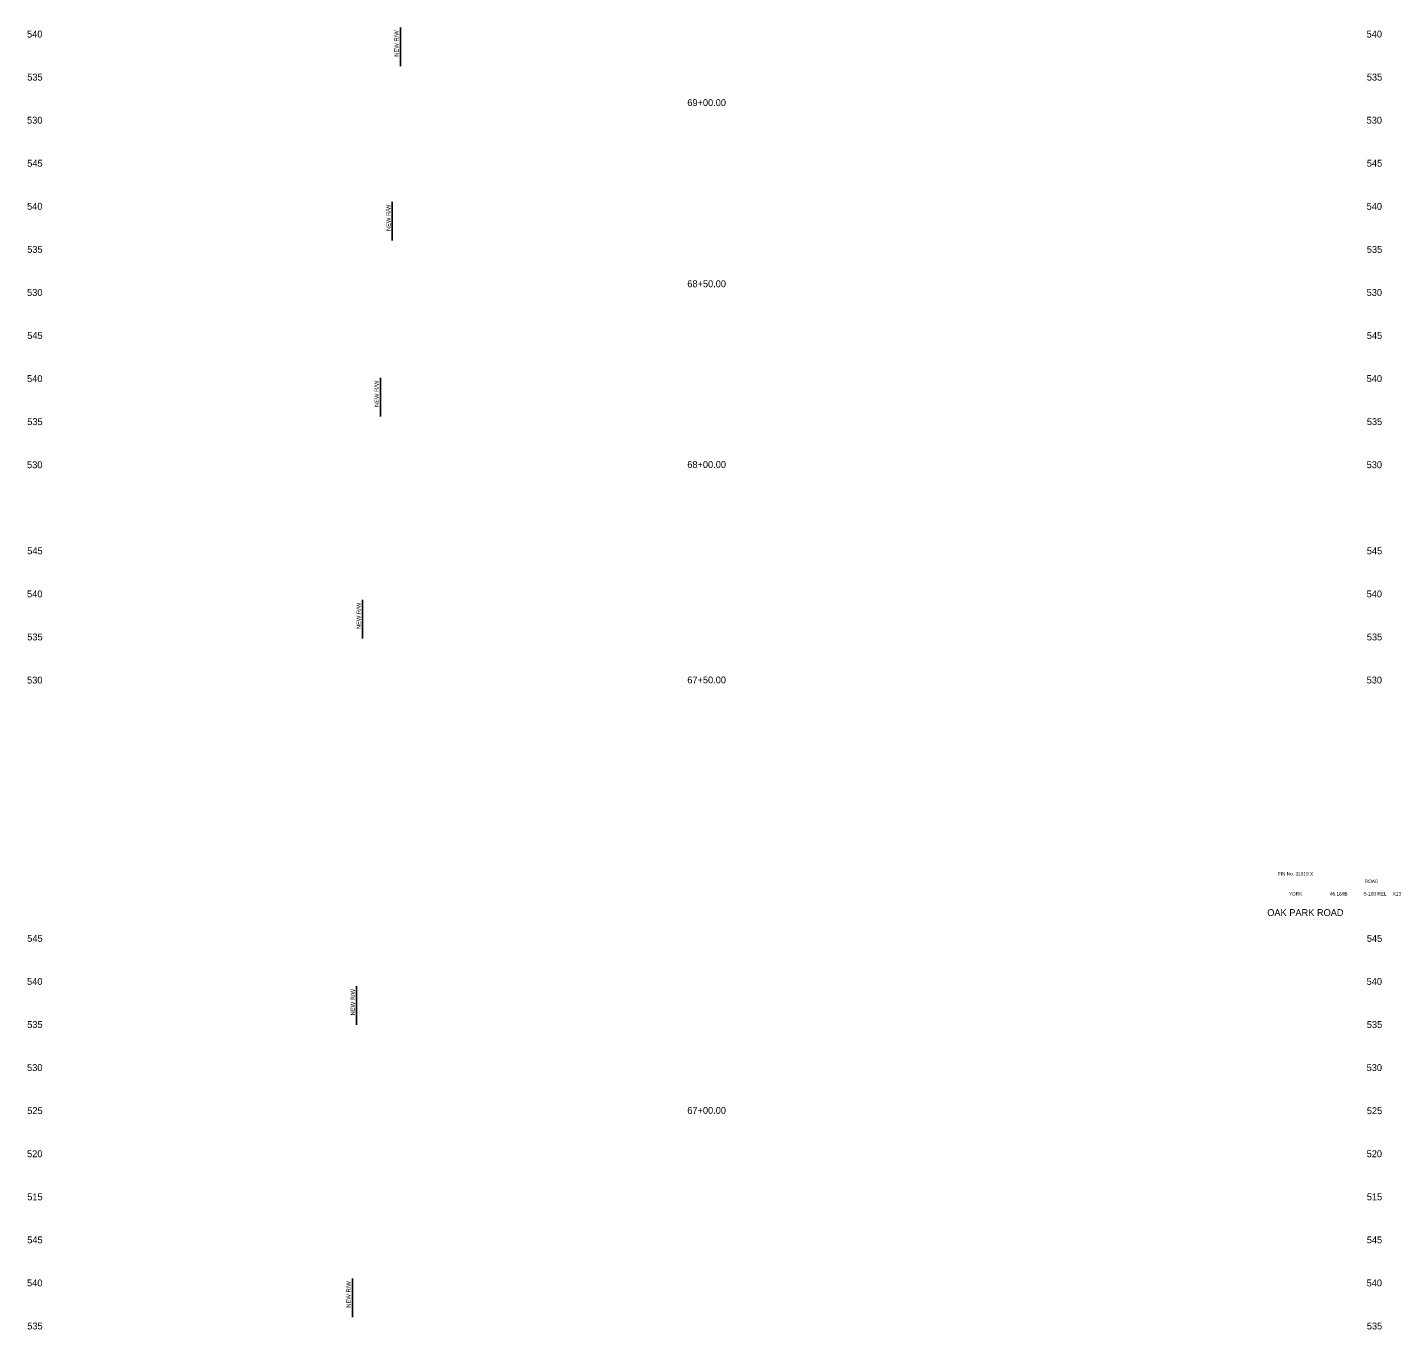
# Model space of a CAD drawing. Extents: x 1001 to 1161, y 1005 to 3518.
# Drawn here: x 1001.2 to 1160.6, y 2430.1 to 2581.3 of the extents above; entities that cross this region are included whole.
import ezdxf

# ---------------------------------------------------------------- set-up
doc = ezdxf.new("R2010")
doc.units = 0
for name, color, linetype in [('RD_SHT_TX', 7, 'Continuous'), ('RD_XS_NewRW', 7, 'Continuous'), ('RD_XS_TX_Elev_EX', 7, 'Continuous'), ('RD_XS_TX_Station', 7, 'Continuous')]:
    doc.layers.add(name, color=color, linetype=linetype)

msp = doc.modelspace()

# ---------------------------------------------------------------- linework, layer by layer
at = {"layer": 'RD_XS_NewRW'}
for p, q in [((1044.47, 2581.27), (1044.47, 2576.77)), ((1043.53, 2561.03), (1043.53, 2556.53)), ((1042.16, 2540.6), (1042.16, 2536.1)), ((1040.08, 2514.81), (1040.08, 2510.31)), ((1039.4, 2469.96), (1039.4, 2465.46)), ((1038.9, 2436.03), (1038.9, 2431.53))]:
    msp.add_line(p, q, dxfattribs=at)

# ---------------------------------------------------------------- texts
at = {"layer": 'RD_SHT_TX'}
for s, height, p in [('PIN No. 31919 X', 0.4, (1146.29, 2482.8)), ('ROAD', 0.4, (1156.41, 2481.93)), ('YORK', 0.4, (1147.61, 2480.48)), ('46.169B', 0.4, (1152.37, 2480.48)), ('S-103 REL', 0.4, (1156.26, 2480.48)), ('X13', 0.4, (1159.65, 2480.48)), ('OAK PARK ROAD', 0.8, (1145.1, 2478.1))]:
    msp.add_text(s, height=height, dxfattribs=at).set_placement(p)
at = {"layer": 'RD_XS_NewRW'}
for p in [(1044.27, 2577.87), (1043.33, 2557.63), (1041.96, 2537.2), (1039.88, 2511.41), (1039.2, 2466.56), (1038.7, 2432.63)]:
    msp.add_text('NEW R/W ', height=0.488, rotation=90, dxfattribs=at).set_placement(p)
at = {"layer": 'RD_XS_TX_Elev_EX'}
for s, p in [('540', (1001.14, 2580.1)), ('540', (1156.64, 2580.1)), ('535', (1001.16, 2575.1)), ('535', (1156.66, 2575.1)), ('530', (1001.14, 2570.1)), ('530', (1156.64, 2570.1)), ('545', (1001.16, 2565.1)), ('545', (1156.66, 2565.1)), ('540', (1001.14, 2560.1)), ('540', (1156.64, 2560.1)), ('535', (1001.16, 2555.1)), ('535', (1156.66, 2555.1)), ('530', (1001.14, 2550.1)), ('530', (1156.64, 2550.1)), ('545', (1001.16, 2545.1)), ('545', (1156.66, 2545.1)), ('540', (1001.14, 2540.1)), ('540', (1156.64, 2540.1)), ('535', (1001.16, 2535.1)), ('535', (1156.66, 2535.1)), ('530', (1001.14, 2530.1)), ('530', (1156.64, 2530.1)), ('545', (1001.16, 2520.1)), ('545', (1156.66, 2520.1)), ('540', (1001.14, 2515.1)), ('540', (1156.64, 2515.1)), ('535', (1001.16, 2510.1)), ('535', (1156.66, 2510.1)), ('530', (1001.14, 2505.1)), ('530', (1156.64, 2505.1)), ('545', (1001.16, 2475.1)), ('545', (1156.66, 2475.1)), ('540', (1001.14, 2470.1)), ('540', (1156.64, 2470.1)), ('535', (1001.16, 2465.1)), ('535', (1156.66, 2465.1)), ('530', (1001.14, 2460.1)), ('530', (1156.64, 2460.1)), ('525', (1001.16, 2455.1)), ('525', (1156.66, 2455.1)), ('520', (1001.14, 2450.1)), ('520', (1156.64, 2450.1)), ('515', (1001.16, 2445.1)), ('515', (1156.66, 2445.1)), ('545', (1001.16, 2440.1)), ('545', (1156.66, 2440.1)), ('540', (1001.14, 2435.1)), ('540', (1156.64, 2435.1)), ('535', (1001.16, 2430.1)), ('535', (1156.66, 2430.1))]:
    msp.add_text(s, height=0.8, dxfattribs=at).set_placement(p)
at = {"layer": 'RD_XS_TX_Station'}
for s, p in [('69+00.00', (1077.78, 2572.14)), ('68+50.00', (1077.78, 2551.11)), ('68+00.00', (1077.78, 2530.12)), ('67+50.00', (1077.78, 2505.11)), ('67+00.00', (1077.78, 2455.13))]:
    msp.add_text(s, height=0.8, dxfattribs=at).set_placement(p)

doc.saveas('drawing.dxf')
